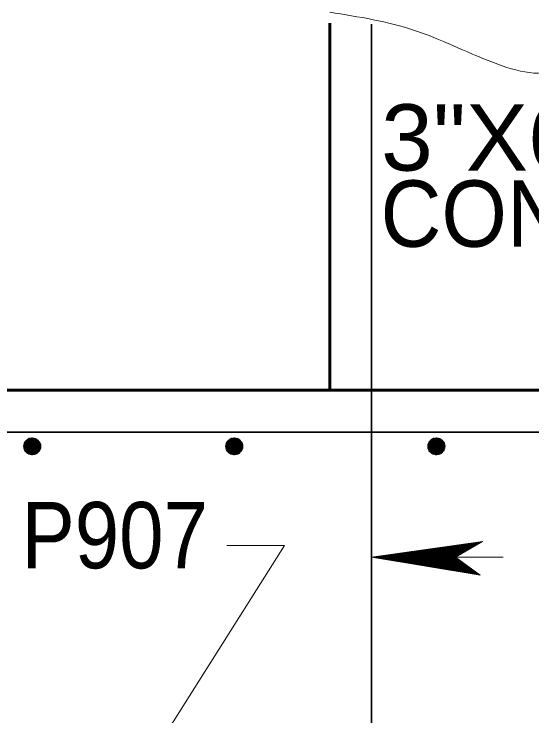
# Model space of a CAD drawing. Extents: x 144 to 252, y 360 to 425.
# Drawn here: x 190.749 to 193.312, y 371.132 to 374.602 of the extents above; entities that cross this region are included whole.
import ezdxf
from ezdxf.enums import TextEntityAlignment as Align

# ---------------------------------------------------------------- set-up
doc = ezdxf.new("R2010")
doc.units = 0
doc.header["$LTSCALE"] = 0.13
for name, color, linetype, lineweight in [('1', 7, 'Continuous', 40), ('14', 7, 'Continuous', 13), ('3', 7, 'Continuous', 13), ('4', 7, 'Continuous', 35)]:
    doc.layers.add(name, color=color, linetype=linetype, lineweight=lineweight)

msp = doc.modelspace()

# ---------------------------------------------------------------- linework, layer by layer
at = {"layer": '1', "lineweight": 60}
msp.add_line((192.3108, 374.5569), (192.3108, 372.7427), dxfattribs=at)
at = {"layer": '1'}
for p, q in [((190.8113, 372.4882), (190.8088, 372.4432)), ((190.8138, 372.4882), (190.8113, 372.4432)), ((190.8113, 372.4882), (190.8713, 372.4782)), ((190.8113, 372.4857), (190.8713, 372.4757)), ((190.8113, 372.4832), (190.8713, 372.4707)), ((190.8113, 372.4807), (190.8713, 372.4682)), ((190.8138, 372.4932), (190.8713, 372.4832)), ((190.8163, 372.4882), (190.8138, 372.4432)), ((190.8188, 372.4882), (190.8163, 372.4432)), ((190.8213, 372.4882), (190.8188, 372.4432)), ((190.8263, 372.4882), (190.8238, 372.4432)), ((190.8288, 372.4882), (190.8263, 372.4432)), ((190.8313, 372.4882), (190.8288, 372.4432)), ((190.8338, 372.4882), (190.8313, 372.4432)), ((190.8363, 372.4882), (190.8338, 372.4432)), ((190.8388, 372.4882), (190.8363, 372.4432)), ((190.8413, 372.4882), (190.8388, 372.4432)), ((190.8463, 372.4857), (190.8413, 372.4407)), ((190.8513, 372.4857), (190.8463, 372.4407)), ((190.8538, 372.4857), (190.8513, 372.4407)), ((190.8538, 372.4857), (190.8513, 372.4407)), ((190.8563, 372.4857), (190.8538, 372.4407)), ((190.8588, 372.4857), (190.8563, 372.4407)), ((190.8613, 372.4857), (190.8588, 372.4407)), ((190.8638, 372.4857), (190.8613, 372.4407)), ((190.8663, 372.4857), (190.8638, 372.4407)), ((190.8688, 372.4857), (190.8663, 372.4407)), ((190.8738, 372.4857), (190.8713, 372.4407)), ((191.8113, 372.4882), (191.8088, 372.4432)), ((191.8138, 372.4882), (191.8113, 372.4432)), ((191.8113, 372.4882), (191.8713, 372.4782)), ((191.8113, 372.4857), (191.8713, 372.4757)), ((191.8113, 372.4832), (191.8713, 372.4707)), ((191.8113, 372.4807), (191.8713, 372.4682)), ((191.8138, 372.4932), (191.8713, 372.4832)), ((191.8163, 372.4882), (191.8138, 372.4432)), ((191.8188, 372.4882), (191.8163, 372.4432)), ((191.8213, 372.4882), (191.8188, 372.4432)), ((191.8263, 372.4882), (191.8238, 372.4432)), ((191.8288, 372.4882), (191.8263, 372.4432)), ((191.8313, 372.4882), (191.8288, 372.4432)), ((191.8338, 372.4882), (191.8313, 372.4432)), ((191.8363, 372.4882), (191.8338, 372.4432)), ((191.8388, 372.4882), (191.8363, 372.4432)), ((191.8413, 372.4882), (191.8388, 372.4432)), ((191.8463, 372.4857), (191.8413, 372.4407)), ((191.8513, 372.4857), (191.8463, 372.4407)), ((191.8538, 372.4857), (191.8513, 372.4407)), ((191.8538, 372.4857), (191.8513, 372.4407)), ((191.8563, 372.4857), (191.8538, 372.4407)), ((191.8588, 372.4857), (191.8563, 372.4407)), ((191.8613, 372.4857), (191.8588, 372.4407)), ((191.8638, 372.4857), (191.8613, 372.4407)), ((191.8663, 372.4857), (191.8638, 372.4407)), ((191.8688, 372.4857), (191.8663, 372.4407)), ((191.8738, 372.4857), (191.8713, 372.4407)), ((192.8113, 372.4882), (192.8088, 372.4432)), ((192.8138, 372.4882), (192.8113, 372.4432)), ((192.8113, 372.4882), (192.8713, 372.4782)), ((192.8113, 372.4857), (192.8713, 372.4757)), ((192.8113, 372.4832), (192.8713, 372.4707)), ((192.8113, 372.4807), (192.8713, 372.4682)), ((192.8138, 372.4932), (192.8713, 372.4832)), ((192.8163, 372.4882), (192.8138, 372.4432)), ((192.8188, 372.4882), (192.8163, 372.4432)), ((192.8213, 372.4882), (192.8188, 372.4432)), ((192.8263, 372.4882), (192.8238, 372.4432)), ((192.8288, 372.4882), (192.8263, 372.4432)), ((192.8313, 372.4882), (192.8288, 372.4432)), ((192.8338, 372.4882), (192.8313, 372.4432)), ((192.8363, 372.4882), (192.8338, 372.4432)), ((192.8388, 372.4882), (192.8363, 372.4432)), ((192.8413, 372.4882), (192.8388, 372.4432)), ((192.8463, 372.4857), (192.8413, 372.4407)), ((192.8513, 372.4857), (192.8463, 372.4407)), ((192.8538, 372.4857), (192.8513, 372.4407)), ((192.8538, 372.4857), (192.8513, 372.4407)), ((192.8563, 372.4857), (192.8538, 372.4407)), ((192.8588, 372.4857), (192.8563, 372.4407)), ((192.8613, 372.4857), (192.8588, 372.4407)), ((192.8638, 372.4857), (192.8613, 372.4407)), ((192.8663, 372.4857), (192.8638, 372.4407)), ((192.8688, 372.4857), (192.8663, 372.4407)), ((192.8738, 372.4857), (192.8713, 372.4407)), ((190.8038, 372.4457), (190.8638, 372.4357)), ((190.8063, 372.4607), (190.8663, 372.4482)), ((190.8063, 372.4532), (190.8663, 372.4432)), ((190.8063, 372.4507), (190.8638, 372.4407)), ((190.8063, 372.4482), (190.8638, 372.4382)), ((190.8088, 372.4732), (190.8688, 372.4632)), ((190.8088, 372.4707), (190.8688, 372.4582)), ((190.8088, 372.4682), (190.8663, 372.4557)), ((190.8088, 372.4657), (190.8663, 372.4532)), ((190.8113, 372.4757), (190.8688, 372.4657)), ((191.8038, 372.4457), (191.8638, 372.4357)), ((191.8063, 372.4607), (191.8663, 372.4482)), ((191.8063, 372.4532), (191.8663, 372.4432)), ((191.8063, 372.4507), (191.8638, 372.4407)), ((191.8063, 372.4482), (191.8638, 372.4382)), ((191.8088, 372.4732), (191.8688, 372.4632)), ((191.8088, 372.4707), (191.8688, 372.4582)), ((191.8088, 372.4682), (191.8663, 372.4557)), ((191.8088, 372.4657), (191.8663, 372.4532)), ((191.8113, 372.4757), (191.8688, 372.4657)), ((192.8038, 372.4457), (192.8638, 372.4357)), ((192.8063, 372.4607), (192.8663, 372.4482)), ((192.8063, 372.4532), (192.8663, 372.4432)), ((192.8063, 372.4507), (192.8638, 372.4407)), ((192.8063, 372.4482), (192.8638, 372.4382)), ((192.8088, 372.4732), (192.8688, 372.4632)), ((192.8088, 372.4707), (192.8688, 372.4582)), ((192.8088, 372.4682), (192.8663, 372.4557)), ((192.8088, 372.4657), (192.8663, 372.4532)), ((192.8113, 372.4757), (192.8688, 372.4657))]:
    msp.add_line(p, q, dxfattribs=at)
at = {"layer": '1', "lineweight": 60}
msp.add_lwpolyline([(188.8108, 369.7427), (198.8108, 369.7427), (198.8108, 372.7427), (194.0608, 372.7427), (194.0608, 372.9927), (193.5608, 372.9927), (193.5608, 372.7427), (188.8108, 372.7427)], close=True, dxfattribs=at)
at = {"layer": '1'}
for points in [[(190.7988, 372.4632), (190.8763, 372.4732), (190.8063, 372.4882), (190.8763, 372.4557), (190.8038, 372.4432), (190.8638, 372.4332), (190.8638, 372.4957), (190.8363, 372.4257), (190.8438, 372.5032), (190.8138, 372.4332), (190.8238, 372.5032), (190.8488, 372.4257), (190.8013, 372.4782), (190.8738, 372.4832), (190.8238, 372.4282), (190.8563, 372.5007), (190.8063, 372.4882), (190.8038, 372.4432), (190.8363, 372.4257), (190.8638, 372.4332), (190.8763, 372.4557), (190.8738, 372.4832), (190.8563, 372.5007), (190.8363, 372.4682), (190.8713, 372.4407), (190.8138, 372.4332), (190.8363, 372.4682), (190.8038, 372.4832), (190.8338, 372.5032), (190.8363, 372.4707), (190.8613, 372.4332), (190.8013, 372.4707), (190.8413, 372.4807), (190.8638, 372.4957)], [(191.7988, 372.4632), (191.8763, 372.4732), (191.8063, 372.4882), (191.8763, 372.4557), (191.8038, 372.4432), (191.8638, 372.4332), (191.8638, 372.4957), (191.8363, 372.4257), (191.8438, 372.5032), (191.8138, 372.4332), (191.8238, 372.5032), (191.8488, 372.4257), (191.8013, 372.4782), (191.8738, 372.4832), (191.8238, 372.4282), (191.8563, 372.5007), (191.8063, 372.4882), (191.8038, 372.4432), (191.8363, 372.4257), (191.8638, 372.4332), (191.8763, 372.4557), (191.8738, 372.4832), (191.8563, 372.5007), (191.8363, 372.4682), (191.8713, 372.4407), (191.8138, 372.4332), (191.8363, 372.4682), (191.8038, 372.4832), (191.8338, 372.5032), (191.8363, 372.4707), (191.8613, 372.4332), (191.8013, 372.4707), (191.8413, 372.4807), (191.8638, 372.4957)], [(192.7988, 372.4632), (192.8763, 372.4732), (192.8063, 372.4882), (192.8763, 372.4557), (192.8038, 372.4432), (192.8638, 372.4332), (192.8638, 372.4957), (192.8363, 372.4257), (192.8438, 372.5032), (192.8138, 372.4332), (192.8238, 372.5032), (192.8488, 372.4257), (192.8013, 372.4782), (192.8738, 372.4832), (192.8238, 372.4282), (192.8563, 372.5007), (192.8063, 372.4882), (192.8038, 372.4432), (192.8363, 372.4257), (192.8638, 372.4332), (192.8763, 372.4557), (192.8738, 372.4832), (192.8563, 372.5007), (192.8363, 372.4682), (192.8713, 372.4407), (192.8138, 372.4332), (192.8363, 372.4682), (192.8038, 372.4832), (192.8338, 372.5032), (192.8363, 372.4707), (192.8613, 372.4332), (192.8013, 372.4707), (192.8413, 372.4807), (192.8638, 372.4957)]]:
    msp.add_lwpolyline(points, dxfattribs=at)
at = {"layer": '1', "lineweight": 13}
msp.add_lwpolyline([(191.802, 371.9742), (192.0869, 371.9742), (190.8471, 370.0117)], dxfattribs=at)
at = {"layer": '1'}
for centre in [(190.8388, 372.4647), (191.8388, 372.4647), (192.8388, 372.4647)]:
    msp.add_circle(centre, 0.0396, dxfattribs=at)
at = {"layer": '1', "lineweight": 13}
msp.add_spline([(192.3108, 374.6112), (192.731, 374.5214), (193.1211, 374.3618), (193.458, 374.3442), (193.5644, 374.4328), (193.8127, 374.4505), (193.919, 374.5392), (194.1672, 374.5037), (194.2382, 374.4328), (194.3091, 374.2732), (194.646, 374.3618), (194.9474, 374.5924), (195.0361, 374.6278), (195.3108, 374.6112)], degree=3, dxfattribs=at)
at = {"layer": '14'}
msp.add_line((193.1698, 371.9162), (192.5173, 371.9162), dxfattribs=at)
at = {"layer": '14', "lineweight": 35}
msp.add_lwpolyline([(192.518, 374.5524), (192.518, 370.0524), (191.518, 370.0524)], dxfattribs=at)
at = {"layer": '3'}
for p, q in [((193.0661, 371.9939), (192.5173, 371.9162)), ((192.9325, 371.916), (193.0661, 371.9939)), ((193.0601, 371.9904), (192.5317, 371.9155)), ((193.0566, 371.9884), (192.5426, 371.9155)), ((193.052, 371.9857), (192.557, 371.9155)), ((193.0479, 371.9833), (192.5697, 371.9155)), ((193.0479, 371.9833), (192.5697, 371.9155)), ((193.0443, 371.9812), (192.5811, 371.9155)), ((193.0397, 371.9785), (192.5955, 371.9155)), ((193.0356, 371.9761), (192.6082, 371.9155)), ((193.0312, 371.9736), (192.622, 371.9155)), ((193.0267, 371.971), (192.6358, 371.9155)), ((193.0225, 371.9685), (192.6491, 371.9155)), ((193.018, 371.9658), (192.663, 371.9155)), ((193.014, 371.9636), (192.6756, 371.9155)), ((193.0102, 371.9613), (192.687, 371.9155)), ((193.0052, 371.9585), (192.7027, 371.9155)), ((193.0008, 371.9558), (192.7165, 371.9155)), ((192.9937, 371.9517), (192.7345, 371.915)), ((192.9968, 371.9536), (192.7361, 371.9166)), ((192.9892, 371.9491), (192.7484, 371.915)), ((192.985, 371.9466), (192.7616, 371.915)), ((192.9835, 371.9457), (192.7707, 371.9155)), ((192.9796, 371.9435), (192.7827, 371.9155)), ((192.9752, 371.9408), (192.7965, 371.9155)), ((192.9702, 371.938), (192.8122, 371.9155)), ((192.9661, 371.9356), (192.8247, 371.9155)), ((192.9618, 371.9331), (192.838, 371.9155)), ((192.958, 371.9308), (192.85, 371.9155)), ((192.9533, 371.9282), (192.8645, 371.9155)), ((192.9489, 371.9256), (192.8783, 371.9155)), ((192.5173, 371.9162), (193.055, 371.8269)), ((192.9327, 371.9162), (192.5173, 371.9162)), ((192.5317, 371.9155), (193.0517, 371.8293)), ((192.5426, 371.9155), (193.0485, 371.8316)), ((192.557, 371.9155), (193.0443, 371.8347)), ((192.5697, 371.9155), (193.0405, 371.8374)), ((192.5811, 371.9155), (193.0372, 371.8398)), ((192.5955, 371.9155), (193.0329, 371.843)), ((192.6082, 371.9155), (193.0292, 371.8458)), ((192.622, 371.9155), (193.0251, 371.8487)), ((192.6358, 371.9155), (193.021, 371.8517)), ((192.6491, 371.9155), (193.0171, 371.8545)), ((192.663, 371.9155), (193.013, 371.8575)), ((192.6756, 371.9155), (193.0092, 371.8602)), ((192.687, 371.9155), (193.0058, 371.8627)), ((192.7027, 371.9155), (193.0012, 371.866)), ((192.7165, 371.9155), (192.9972, 371.869)), ((192.7345, 371.915), (192.9929, 371.8721)), ((192.7484, 371.915), (192.9887, 371.8751)), ((192.7616, 371.915), (192.9849, 371.8779)), ((192.7707, 371.9155), (192.9812, 371.8807)), ((192.7827, 371.9155), (192.9776, 371.8832)), ((192.7965, 371.9155), (192.9735, 371.8862)), ((192.8122, 371.9155), (192.9688, 371.8895)), ((192.8247, 371.9155), (192.9652, 371.8922)), ((192.838, 371.9155), (192.9613, 371.8951)), ((192.85, 371.9155), (192.9577, 371.8977)), ((192.8645, 371.9155), (192.9534, 371.9007)), ((192.8783, 371.9155), (192.9493, 371.9038)), ((192.9448, 371.9232), (192.891, 371.9155)), ((192.891, 371.9155), (192.9456, 371.9065)), ((192.9042, 371.9155), (192.9417, 371.9093)), ((192.9396, 371.9202), (192.9145, 371.9166)), ((192.9369, 371.9186), (192.9157, 371.9155)), ((192.9157, 371.9155), (192.9382, 371.9117)), ((192.9258, 371.9155), (192.9352, 371.914)), ((193.055, 371.8269), (192.9325, 371.916))]:
    msp.add_line(p, q, dxfattribs=at)
at = {"layer": '4'}
msp.add_line((189.0608, 372.5343), (198.6356, 372.5343), dxfattribs=at)

# ---------------------------------------------------------------- texts
at = {"layer": '14'}
for s, width, p in [('3"X6" KEY', 1.05, (192.5652, 373.8279)), ('CONST. JT.', 0.95, (192.5626, 373.4513))]:
    msp.add_text(s, height=0.3281, dxfattribs=dict(at, width=width)).set_placement(p)
at = {"layer": '14', "width": 0.9}
msp.add_text('P907', height=0.3281, dxfattribs=at).set_placement((191.2472, 371.8614), align=Align.CENTER)

doc.saveas('drawing.dxf')
